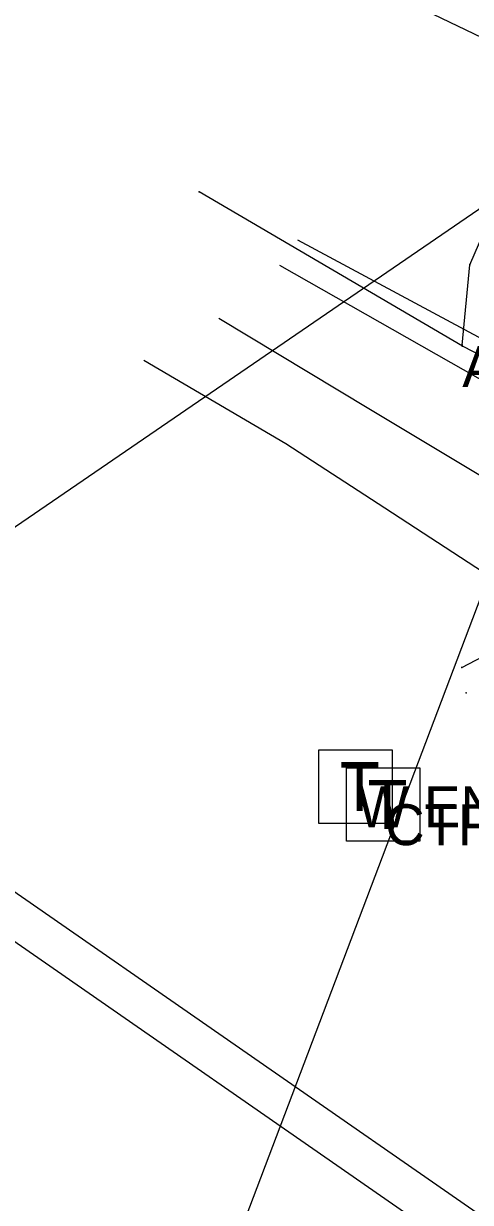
# Model space of a CAD drawing. Extents: x 997398 to 1003416, y 334596 to 337085.
# Drawn here: x 999358.1 to 999412.9, y 336058.3 to 336202.6 of the extents above; entities that cross this region are included whole.
import ezdxf

# ---------------------------------------------------------------- set-up
doc = ezdxf.new("R2010")
doc.units = 0
for name, color, linetype in [('Default', 7, 'Continuous'), ('S_DITCHLINE', 7, 'Continuous'), ('S_EDGE_CONCRETE', 7, 'Continuous'), ('S_EDGE_PAVEMENT', 7, 'Continuous'), ('S_FIBER_OPTIC_CABLE', 7, 'Continuous'), ('S_GAS_UTILITIES', 7, 'Continuous'), ('S_GAS_UTILITIES_ANNOT', 7, 'Continuous'), ('S_PAVEMENT_CROWN', 7, 'Continuous'), ('S_RAILROAD', 7, 'Continuous'), ('S_SANITARY_SEWER', 7, 'Continuous'), ('S_TELEPHONE_UTILITIES', 7, 'Continuous'), ('S_TELEPHONE_UTILITIES_ANNOT', 7, 'Continuous'), ('S_UTL_PT_SYM', 7, 'Continuous')]:
    doc.layers.add(name, color=color, linetype=linetype)

msp = doc.modelspace()

# ---------------------------------------------------------------- linework, layer by layer
at = {"layer": 'Default'}
msp.add_line((998964.3, 335872.43), (999557.02, 336277.74), dxfattribs=at)
at = {"layer": 'S_DITCHLINE'}
msp.add_lwpolyline([(999420.52, 336160.63), (999406.13, 336168.34), (999391.75, 336176.05)], dxfattribs=at)
at = {"layer": 'S_EDGE_CONCRETE'}
msp.add_lwpolyline([(999522.25, 336257.36), (999519.69, 336264.47), (999515.62, 336268.99), (999499.47, 336276.9), (999496.42, 336275.19), (999489.21, 336260.65), (999482, 336246.12), (999471.33, 336224.11), (999460.67, 336202.1), (999451.61, 336182.6), (999449.32, 336172.31), (999448.89, 336161.32), (999430.05, 336166.38), (999428.87, 336186.15), (999424.48, 336195.98), (999405.32, 336205.16)], dxfattribs=at)
at = {"layer": 'S_EDGE_PAVEMENT'}
for points in [[(999389.47, 336172.99), (999406.88, 336163.14), (999424.28, 336153.28), (999429.24, 336157.24), (999430.03, 336166.07), (999448.96, 336161.03), (999448.69, 336144.53), (999451.98, 336140.38), (999457.91, 336139.71), (999469.47, 336141.47), (999474.09, 336143.82)], [(999458.08, 336107.37), (999454.78, 336113.28), (999436.87, 336123.07), (999425.69, 336129.23), (999414.5, 336135.38), (999402.39, 336143.26), (999390.28, 336151.14), (999372.85, 336161.33)]]:
    msp.add_lwpolyline(points, dxfattribs=at)
at = {"layer": 'S_FIBER_OPTIC_CABLE'}
msp.add_line((999411.83, 336123.78), (999415.36, 336125.59), dxfattribs=at)
at = {"layer": 'S_GAS_UTILITIES'}
for p, q in [((999412.82, 336173.07), (999420.76, 336191.44)), ((999411.9, 336163.1), (999379.64, 336181.98)), ((999411.87, 336163.23), (999412.82, 336173.07)), ((999449.32, 336143.79), (999411.9, 336163.1))]:
    msp.add_line(p, q, dxfattribs=at)
at = {"layer": 'S_PAVEMENT_CROWN'}
msp.add_lwpolyline([(999382.04, 336166.53), (999400.43, 336155.48), (999418.81, 336144.44), (999430.29, 336138.14), (999441.77, 336131.85), (999453.26, 336125.55), (999464.74, 336119.25)], dxfattribs=at)
at = {"layer": 'S_RAILROAD'}
for p, q in [((999425.68, 336048.66), (999340.2, 336107.93)), ((999337.53, 336103.75), (999424.31, 336043.62))]:
    msp.add_line(p, q, dxfattribs=at)
at = {"layer": 'S_SANITARY_SEWER'}
msp.add_line((999358.45, 335985.56), (999416.74, 336139.2), dxfattribs=at)
at = {"layer": 'S_TELEPHONE_UTILITIES'}
for points in [[(999394.31, 336104.69), (999394.31, 336113.69), (999403.31, 336113.69), (999403.31, 336104.69)], [(999397.71, 336102.5), (999397.71, 336111.5), (999406.71, 336111.5), (999406.71, 336102.5)]]:
    msp.add_lwpolyline(points, close=True, dxfattribs=at)
at = {"layer": 'S_UTL_PT_SYM'}
for points in [[(999379.64, 336181.98), (999379.64, 336182.03), (999379.64, 336181.98), (999379.59, 336181.98), (999379.64, 336181.98), (999379.64, 336181.93), (999379.64, 336181.98), (999379.69, 336181.98)], [(999412.82, 336173.07), (999412.82, 336173.12), (999412.82, 336173.07), (999412.77, 336173.07), (999412.82, 336173.07), (999412.82, 336173.02), (999412.82, 336173.07), (999412.87, 336173.07)], [(999411.87, 336163.23), (999411.87, 336163.28), (999411.87, 336163.23), (999411.82, 336163.23), (999411.87, 336163.23), (999411.87, 336163.18), (999411.87, 336163.23), (999411.92, 336163.23)], [(999411.9, 336163.1), (999411.9, 336163.15), (999411.9, 336163.1), (999411.85, 336163.1), (999411.9, 336163.1), (999411.9, 336163.05), (999411.9, 336163.1), (999411.95, 336163.1)], [(999411.83, 336123.78), (999411.83, 336123.83), (999411.83, 336123.78), (999411.78, 336123.78), (999411.83, 336123.78), (999411.83, 336123.73), (999411.83, 336123.78), (999411.88, 336123.78)], [(999412.38, 336120.66), (999412.38, 336120.71), (999412.38, 336120.66), (999412.33, 336120.66), (999412.38, 336120.66), (999412.38, 336120.61), (999412.38, 336120.66), (999412.43, 336120.66)]]:
    msp.add_lwpolyline(points, dxfattribs=at)

# ---------------------------------------------------------------- texts
at = {"layer": 'S_GAS_UTILITIES_ANNOT'}
msp.add_text('AT TEE', height=5, dxfattribs=at).set_placement((999411.9, 336158.1))
at = {"layer": 'S_TELEPHONE_UTILITIES'}
for p in [(999396.87, 336106.19), (999400.27, 336104)]:
    msp.add_text('T', height=6, rotation=360, dxfattribs=at).set_placement(p)
at = {"layer": 'S_TELEPHONE_UTILITIES_ANNOT'}
for s, p in [('W END', (999399.03, 336104.21)), ('CTR OF VAULT,2.0NS X4.0.. ..EW,', (999402.44, 336102.02))]:
    msp.add_text(s, height=5, dxfattribs=at).set_placement(p)

doc.saveas('drawing.dxf')
